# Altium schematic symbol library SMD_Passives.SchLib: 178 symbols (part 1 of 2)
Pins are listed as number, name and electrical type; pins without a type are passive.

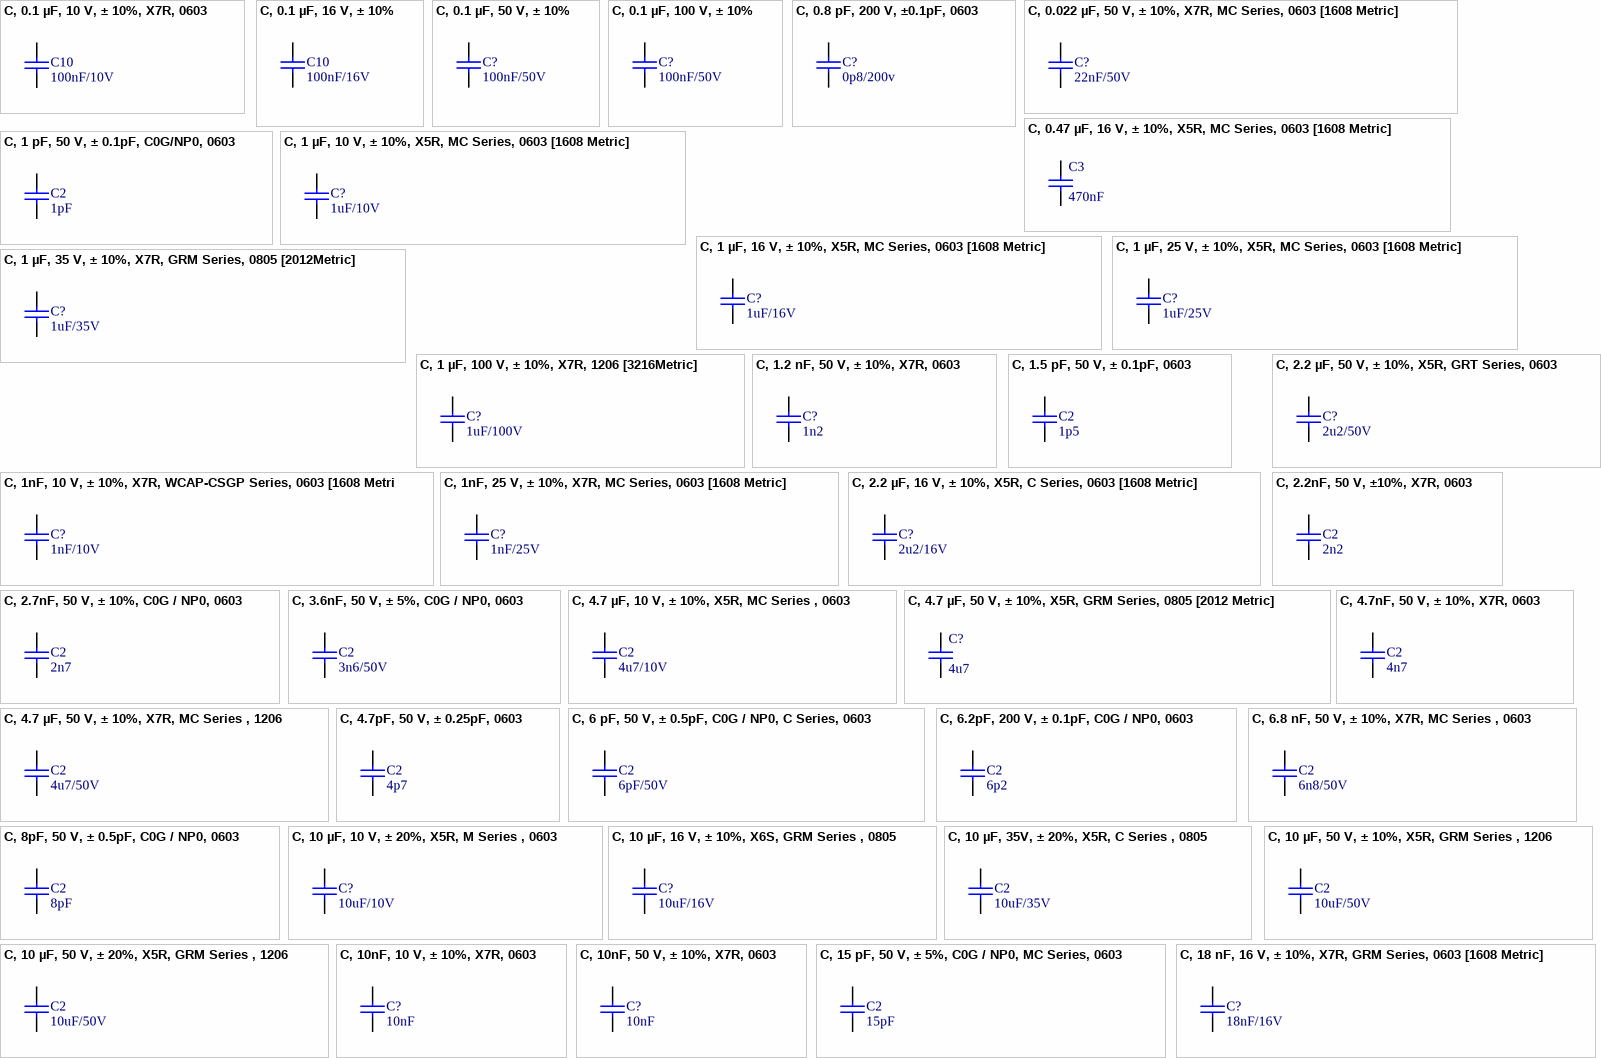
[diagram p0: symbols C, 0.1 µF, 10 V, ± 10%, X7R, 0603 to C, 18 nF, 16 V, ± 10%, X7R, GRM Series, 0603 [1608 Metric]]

## C, 0.1 µF, 10 V, ± 10%, X7R, 0603
designator C10, comment 100nF/10V
SMD Multilayer Ceramic Capacitor, 0603 [1608 Metric], 0.1 µF, 10 V, ± 10%, X7R, MC Series; MPN: MC0603B104K100CT; Type: MLCC; VoltageRating: 10V; MF: Multicomp; Capacitance: 100nF
footprint C0603 (0603 ceramic capacitor)
footprint C0603_BYPADD
footprint C0603_BYPASS
pins: 1, 2

## C, 0.1 µF, 16 V, ± 10%
designator C10, comment 100nF/16V
SMD Multilayer Ceramic Capacitor, 0603 [1608 Metric], 0.1 µF, 16 V, ± 10%, X7R, MC Series; MPN: MC0603B104K160CT; Type: MLCC; VoltageRating: 16V; ComponentLinknDescription: Datasheet; MF: Multicomp; Capacitance: 100nF
footprint C0603 (0603 ceramic capacitor)
footprint C0603_BYPADD
footprint C0603_BYPASS
pins: 1, 2

## C, 0.1 µF, 50 V, ± 10%
designator C?, comment 100nF/50V
SMD Multilayer Ceramic Capacitor, 0603 [1608 Metric], 0.1 µF, 50 V, ± 10%, X7R, MC Series; MPN: 885012206095; Type: MLCC; VoltageRating: 50V; ComponentLinknDescription: Datasheet; MF: Wurth Electronics; Capacitance: 100nF
footprint C0603 (0603 ceramic capacitor)
footprint C0603_BYPADD
footprint C0603_BYPASS
pins: 1, 2

## C, 0.1 µF, 100 V, ± 10%
designator C?, comment 100nF/50V
SMD Multilayer Ceramic Capacitor, 1812 [4532 Metric], 0.1 µF, 100 V, ± 5%, C0G / NP0, C Series; MPN: 885012206095; Type: MLCC; VoltageRating: 50V; ComponentLinknDescription: Datasheet; MF: Wurth Electronics; Capacitance: 100nF; Precision: 10%
footprint C1812 (1812 capacitor)
pins: 1, 2

## C, 0.8 pF, 200 V, ±0.1pF, 0603
designator C?, comment 0p8/200v
SMD Multilayer Ceramic Capacitor, 0603 [1608 Metric], 0.8 pF, 2000 V, ±0.1pF, C0G; MPN: 06032U0R8BAT2A; Type: MLCC; VoltageRating: 200v; ComponentLinknDescription: Datasheet; MF: AVX; Capacitance: 0p8
footprint C0603 (0603 ceramic capacitor)
pins: 1, 2

## C, 0.022 µF, 50 V, ± 10%, X7R, MC Series, 0603 [1608 Metric]
designator C?, comment 22nF/50V
SMD Multilayer Ceramic Capacitor, 0603 [1608 Metric], 0.022 µF, 50 V, ± 10%, X7R, MC Series; MPN: MC0603B223K500CT; Type: MLCC; VoltageRating: 50V; MF: MULTICOMP; Capacitance: 22nF
footprint C0603 (0603 ceramic capacitor)
pins: 1, 2

## C, 0.47 µF, 16 V, ± 10%, X5R, MC Series, 0603 [1608 Metric]
designator C3, comment 470nF
SMD Multilayer Ceramic Capacitor, 0603 [1608 Metric], 0.47 µF, 16 V, ± 10%, X5R, MC Series; MPN: MC0603X474K160CT; Type: MLCC; Voltage rating: 16V; ComponentLinknDescription: Datasheet; MF: Multicomp
footprint C0603 (0603 ceramic capacitor)
pins: 1, 2

## C, 1 pF, 50 V, ± 0.1pF, C0G/NP0, 0603
designator C2, comment 1pF
SMD Multilayer Ceramic Capacitor, 0603 [1608 Metric], 1 pF, 50 V, ± 0.1pF, C0G / NP0, GRM Series; MPN: GRM1885C1H1R0BA01D; Type: MLCC; VoltageRating: 50V; MF: MURATA
footprint C0603 (0603 ceramic capacitor)
pins: 1, 2

## C, 1 µF, 10 V, ± 10%, X5R, MC Series, 0603 [1608 Metric]
designator C?, comment 1uF/10V
SMD Multilayer Ceramic Capacitor, 0603 [1608 Metric], 1 µF, 10 V, ± 10%, X5R, MC Series; MPN: MC0603X105K100CT; Type: MLCC; VoltageRating: 10V; MF: MULTICOMP; Capacitance: 1uF
footprint C0603 (0603 ceramic capacitor)
pins: 1, 2

## C, 1 µF, 16 V, ± 10%, X5R, MC Series, 0603 [1608 Metric]
designator C?, comment 1uF/16V
SMD Multilayer Ceramic Capacitor, 0603 [1608 Metric], 1 µF, 16 V, ± 10%, X5R, MC Series; MPN: MC0603X105K160CT; Type: MLCC; VoltageRating: 16V; MF: MULTICOMP; Capacitance: 1uF
footprint C0603 (0603 ceramic capacitor)
pins: 1, 2

## C, 1 µF, 25 V, ± 10%, X5R, MC Series, 0603 [1608 Metric]
designator C?, comment 1uF/25V
SMD Multilayer Ceramic Capacitor, 0603 [1608 Metric], 1 µF, 25 V, ± 10%, X5R, MC Series; MPN: MC0603X105K250CT; Type: MLCC; VoltageRating: 25V; MF: MULTICOMP; Capacitance: 1uF
footprint C0603 (0603 ceramic capacitor)
pins: 1, 2

## C, 1 µF, 35 V, ± 10%, X7R, GRM Series, 0805 [2012Metric]
designator C?, comment 1uF/35V
SMD Multilayer Ceramic Capacitor, 0805 [2012 Metric], 1 µF, 35 V, ± 10%, X7R, GCM Series; MPN: GCM21BR7YA105KA55L; Type: MLCC; VoltageRating: 35V; MF: MURATA; Capacitance: 1uF
footprint C0603 (0603 ceramic capacitor)
pins: 1, 2

## C, 1 µF, 100 V, ± 10%, X7R, 1206 [3216Metric]
designator C?, comment 1uF/100V
SMD Multilayer Ceramic Capacitor, 1206 [3216 Metric], 1 µF, 100 V, ± 10%, X7R; MPN: 12061C105KAT2A; Type: MLCC; VoltageRating: 100V; MF: AVX; Capacitance: 1uF
footprint C1206 (1206 ceramic capacitor)
pins: 1, 2

## C, 1.2 nF, 50 V, ± 10%, X7R, 0603
designator C?, comment 1n2
SMD Multilayer Ceramic Capacitor, General Purpose, 0603 [1608 Metric], 1200 pF, 50 V, ± 10%, X7R; MPN: 0603B122K500CT; Type: MLCC; VoltageRating: 50V; MF: WALSIN
footprint C0603 (0603 ceramic capacitor)
pins: 1, 2

## C, 1.5 pF, 50 V, ± 0.1pF, 0603
designator C2, comment 1p5
SMD Multilayer Ceramic Capacitor, Hi-Q®, 0603 [1608 Metric], 1.5 pF, 250 V, ± 0.1pF, ML Series; MPN: ML03V11R5BAT2A; Type: MLCC; VoltageRating: 50V; MF: AVX
footprint C0603 (0603 ceramic capacitor)
pins: 1, 2

## C, 1nF, 10 V, ± 10%, X7R, WCAP-CSGP Series, 0603 [1608 Metric]
designator C?, comment 1nF/10V
SMD Multilayer Ceramic Capacitor, 0603 [1608 Metric], 1000 pF, 25 V, ± 10%, X7R, MC Series; MPN: 885012206014; Type: MLCC; VoltageRating: 10V; MF: WURTH ELECTRONIC; Capacitance: 1nF
footprint C0603 (0603 ceramic capacitor)
pins: 1, 2

## C, 1nF, 25 V, ± 10%, X7R, MC Series, 0603 [1608 Metric]
designator C?, comment 1nF/25V
SMD Multilayer Ceramic Capacitor, 0603 [1608 Metric], 1000 pF, 25 V, ± 10%, X7R, MC Series; MPN: MC0603B102K250CT; Type: MLCC; VoltageRating: 25V; MF: MULTICOMP; Capacitance: 1nF
footprint C0603 (0603 ceramic capacitor)
pins: 1, 2

## C, 2.2 µF, 16 V, ± 10%, X5R, C Series, 0603 [1608 Metric]
designator C?, comment 2u2/16V
SMD Multilayer Ceramic Capacitor, 0603 [1608 Metric], 2.2 µF, 16 V, ± 10%, X5R, C Series; MPN: C0603C225K4PACTU; Type: MLCC; VoltageRating: 16V; MF: KEMET; Capacitance: 2u2
footprint C0603 (0603 ceramic capacitor)
pins: 1, 2

## C, 2.2 µF, 50 V, ± 10%, X5R, GRT Series, 0603
designator C?, comment 2u2/50V
SMD Multilayer Ceramic Capacitor, 0603 [1608 Metric], 2.2 µF, 50 V, ± 10%, X5R, GRT Series; MPN: GRT188R61H225KE13D; Type: MLCC; VoltageRating: 50V; MF: MURATA; Capacitance: 2u2
footprint C0603 (0603 ceramic capacitor)
pins: 1, 2

## C, 2.2nF, 50 V, ±10%, X7R, 0603
designator C2, comment 2n2
SMD Multilayer Ceramic Capacitor, 0603 [1608 Metric], 2200 pF, 50 V, ± 10%, X7R, MC Series; MPN: MC0603B222K500CT; Type: MLCC; VoltageRating: 50V; MF: MULTICOMP
footprint C0603 (0603 ceramic capacitor)
pins: 1, 2

## C, 2.7nF, 50 V, ± 10%, C0G / NP0, 0603
designator C2, comment 2n7
SMD Multilayer Ceramic Capacitor, 0603 [1608 Metric], 2700 pF, 50 V, ± 10%, X7R, MC Series; MPN: MC0603B272K500CT; Type: MLCC; VoltageRating: 50V; MF: MULTICOMP
footprint C0603 (0603 ceramic capacitor)
pins: 1, 2

## C, 3.6nF, 50 V, ± 5%, C0G / NP0, 0603
designator C2, comment 3n6/50V
SMD Multilayer Ceramic Capacitor, 0603 [1608 Metric], 3600 pF, 50 V, ± 5%, C0G / NP0, C Series; MPN: C1608C0G1H151J080AA; Type: MLCC; VoltageRating: 50V; MF: TDK; Capacitance: 3n6
footprint C0603 (0603 ceramic capacitor)
pins: 1, 2

## C, 4.7 µF, 10 V, ± 10%, X5R, MC Series , 0603
designator C2, comment 4u7/10V
SMD Multilayer Ceramic Capacitor, 0603 [1608 Metric], 4.7 µF, 10 V, ± 10%, X5R, MC Series; MPN: MC0603X475K100CT; Type: MLCC; VoltageRating: 10V; MF: MULTICOMP; Capacitance: 4u7
footprint C0603 (Footprint not found)
pins: 1, 2

## C, 4.7 µF, 50 V, ± 10%, X5R, GRM Series, 0805 [2012 Metric]
designator C?, comment 4u7
SMD Multilayer Ceramic Capacitor, 0805 [2012 Metric], 4.7 µF, 50 V, ± 10%, X5R, GRM Series; MPN: GRM21BR61H475KE51L; Type: MLCC; Voltage rating: 50V; ComponentLinknDescription: Datasheet; MF: MURATA
footprint C0805 (0805 ceramic capacitor)
pins: 1, 2

## C, 4.7 µF, 50 V, ± 10%, X7R, MC Series , 1206
designator C2, comment 4u7/50V
SMD Multilayer Ceramic Capacitor, 1206 [3216 Metric], 4.7 µF, 50 V, ± 10%, X7R, MC Series; MPN: MC1206B475K500CT; Type: MLCC; VoltageRating: 50V; MF: MULTICOMP; Capacitance: 4u7
footprint C1206 (1206 ceramic capacitor)
pins: 1, 2

## C, 4.7nF, 50 V, ± 10%, X7R, 0603
designator C2, comment 4n7
SMD Multilayer Ceramic Capacitor, 0603 [1608 Metric], 4700 pF, 50 V, ± 10%, X7R, MC Series; MPN: MC0603B472K500CT; Type: MLCC; VoltageRating: 50V; MF: MULTICOMP
footprint C0603 (0603 ceramic capacitor)
pins: 1, 2

## C, 4.7pF, 50 V, ± 0.25pF, 0603
designator C2, comment 4p7
SMD Multilayer Ceramic Capacitor, General Purpose, 0603 [1608 Metric], 4.7 pF, 50 V, ± 0.25pF; MPN: MC0603B471J500CT; Type: MLCC; VoltageRating: 50V; MF: MULTICOMP
footprint C0603 (0603 ceramic capacitor)
pins: 1, 2

## C, 6 pF, 50 V, ± 0.5pF, C0G / NP0, C Series, 0603
designator C2, comment 6pF/50V
SMD Multilayer Ceramic Capacitor, 0603 [1608 Metric], 6 pF, 50 V, ± 0.5pF, C0G / NP0, C Series; MPN: C1608C0G1H060D080AA; Type: MLCC; VoltageRating: 50V; MF: TDK; Capacitance: 6pF
footprint C0603 (Footprint not found)
pins: 1, 2

## C, 6.2pF, 200 V, ± 0.1pF, C0G / NP0, 0603
designator C2, comment 6p2
Multilayer Ceramic Capacitors MLCC - SMD/SMT 200V 6.2pF C0G 0603 .1pF Tol; MPN: 06032U6R2BAT2A; Characteristic: C0G/NP0; MF: AVX; Precision: 0.1pF
footprint C0603 (0603 ceramic capacitor)
pins: 1, 2

## C, 6.8 nF, 50 V, ± 10%, X7R, MC Series , 0603
designator C2, comment 6n8/50V
SMD Multilayer Ceramic Capacitor, 0603 [1608 Metric], 6800 pF, 50 V, ± 10%, X7R, MC Series; MPN: MC0603B682K500CT; Type: MLCC; VoltageRating: 50V; MF: MULTICOMP; Capacitance: 6n8
footprint C0603 (Footprint not found)
pins: 1, 2

## C, 8pF, 50 V, ± 0.5pF, C0G / NP0, 0603
designator C2, comment 8pF
SMD Multilayer Ceramic Capacitor, 0603 [1608 Metric], 8 pF, 50 V, ± 0.5pF, C0G / NP0, MC Series; MPN: MC0603N8R0D500CT; Type: MLCC; VoltageRating: 50; MF: MULTICOMP
footprint C0603 (0603 ceramic capacitor)
pins: 1, 2

## C, 10 µF, 10 V, ± 20%, X5R, M Series , 0603
designator C?, comment 10uF/10V
SMD Multilayer Ceramic Capacitor, 0603 [1608 Metric], 10 µF, 10 V, ± 20%, X5R, M Series; MPN: LMK107BBJ106MALT; Type: MLCC; VoltageRating: 10V; MF: TAIYO YUDEN; Capacitance: 10uF
footprint C0603 (0603 ceramic capacitor)
pins: 1, 2

## C, 10 µF, 16 V, ± 10%, X6S, GRM Series , 0805
designator C?, comment 10uF/16V
SMD Multilayer Ceramic Capacitor, 0603 [1608 Metric], 10 µF, 10 V, ± 20%, X5R, M SeriesSMD Multilayer Ceramic Capacitor, 0805 [2012 Metric], 10 µF, 16 V, ± 10%, X6S, GRM Series; MPN: GRM21BC81C106KE15L; Type: MLCC; VoltageRating: 16V; MF: MURATA; Capacitance: 10uF
footprint C0805 (0805 ceramic capacitor)
pins: 1, 2

## C, 10 µF, 35V, ± 20%, X5R, C Series , 0805
designator C2, comment 10uF/35V
SMD Multilayer Ceramic Capacitor, 0805 [2012 Metric], 10 µF, 35 V, ± 20%, X5R, C Series; MPN: C2012X5R1V106M085AC; Type: MLCC; VoltageRating: 35V; MF: TDK; Capacitance: 10uF
footprint C0805 (0805 ceramic capacitor)
pins: 1, 2

## C, 10 µF, 50 V, ± 10%, X5R, GRM Series , 1206
designator C2, comment 10uF/50V
SMD Multilayer Ceramic Capacitor, 1206 [3216 Metric], 10 µF, 50 V, ± 10%, X5R, C Series; MPN: C3216X5R1H106K160AB; Type: MLCC; VoltageRating: 50V; MF: TDK; Capacitance: 10uF
footprint C1206 (1206 ceramic capacitor)
pins: 1, 2

## C, 10 µF, 50 V, ± 20%, X5R, GRM Series , 1206
designator C2, comment 10uF/50V
SMD Multilayer Ceramic Capacitor, 1206 [3216 Metric], 10 µF, 50 V, ± 20%, X5R, GRM Series; MPN: GRM31CR61H106MA12L; Type: MLCC; VoltageRating: 50V; MF: MURATA; Capacitance: 10uF
footprint C1206 (1206 ceramic capacitor)
pins: 1, 2

## C, 10nF, 10 V, ± 10%, X7R, 0603
designator C?, comment 10nF
SMD Multilayer Ceramic Capacitor, 0603 [1608 Metric], 0.01 µF, 10 V, ± 10%, X7R, MCSH Series; MPN: MCSH18B103K100CT; Type: MLCC; VoltageRating: 10V; MF: MULTICOMP
footprint C0603 (0603 ceramic capacitor)
pins: 1, 2

## C, 10nF, 50 V, ± 10%, X7R, 0603
designator C?, comment 10nF
SMD Multilayer Ceramic Capacitor, 0603 [1608 Metric], 0.01 µF, 50 V, ± 10%, X7R, MC Series; MPN: MC0603B103K500CT; Type: MLCC; VoltageRating: 50V; MF: MULTICOMP
footprint C0603 (0603 ceramic capacitor)
pins: 1, 2

## C, 15 pF, 50 V, ± 5%, C0G / NP0, MC Series, 0603
designator C2, comment 15pF
SMD Multilayer Ceramic Capacitor, 0603 [1608 Metric], 15 pF, 50 V, ± 5%, C0G / NP0, MC Series; MPN: MC0603N150J500CT; Type: MLCC; VoltageRating: 50V; MF: MULTICOMP
footprint C0603 (0603 ceramic capacitor)
pins: 1, 2

## C, 18 nF, 16 V, ± 10%, X7R, GRM Series, 0603 [1608 Metric]
designator C?, comment 18nF/16V
SMD Multilayer Ceramic Capacitor, 0603 [1608 Metric], 18 nF, 16 V, ± 10%, X7R, GRM Series; MPN: GRM188R71C183KA01D; Type: MLCC; VoltageRating: 16V; MF: MURATA; Capacitance: 18nF
footprint C0603 (0603 ceramic capacitor)
pins: 1, 2

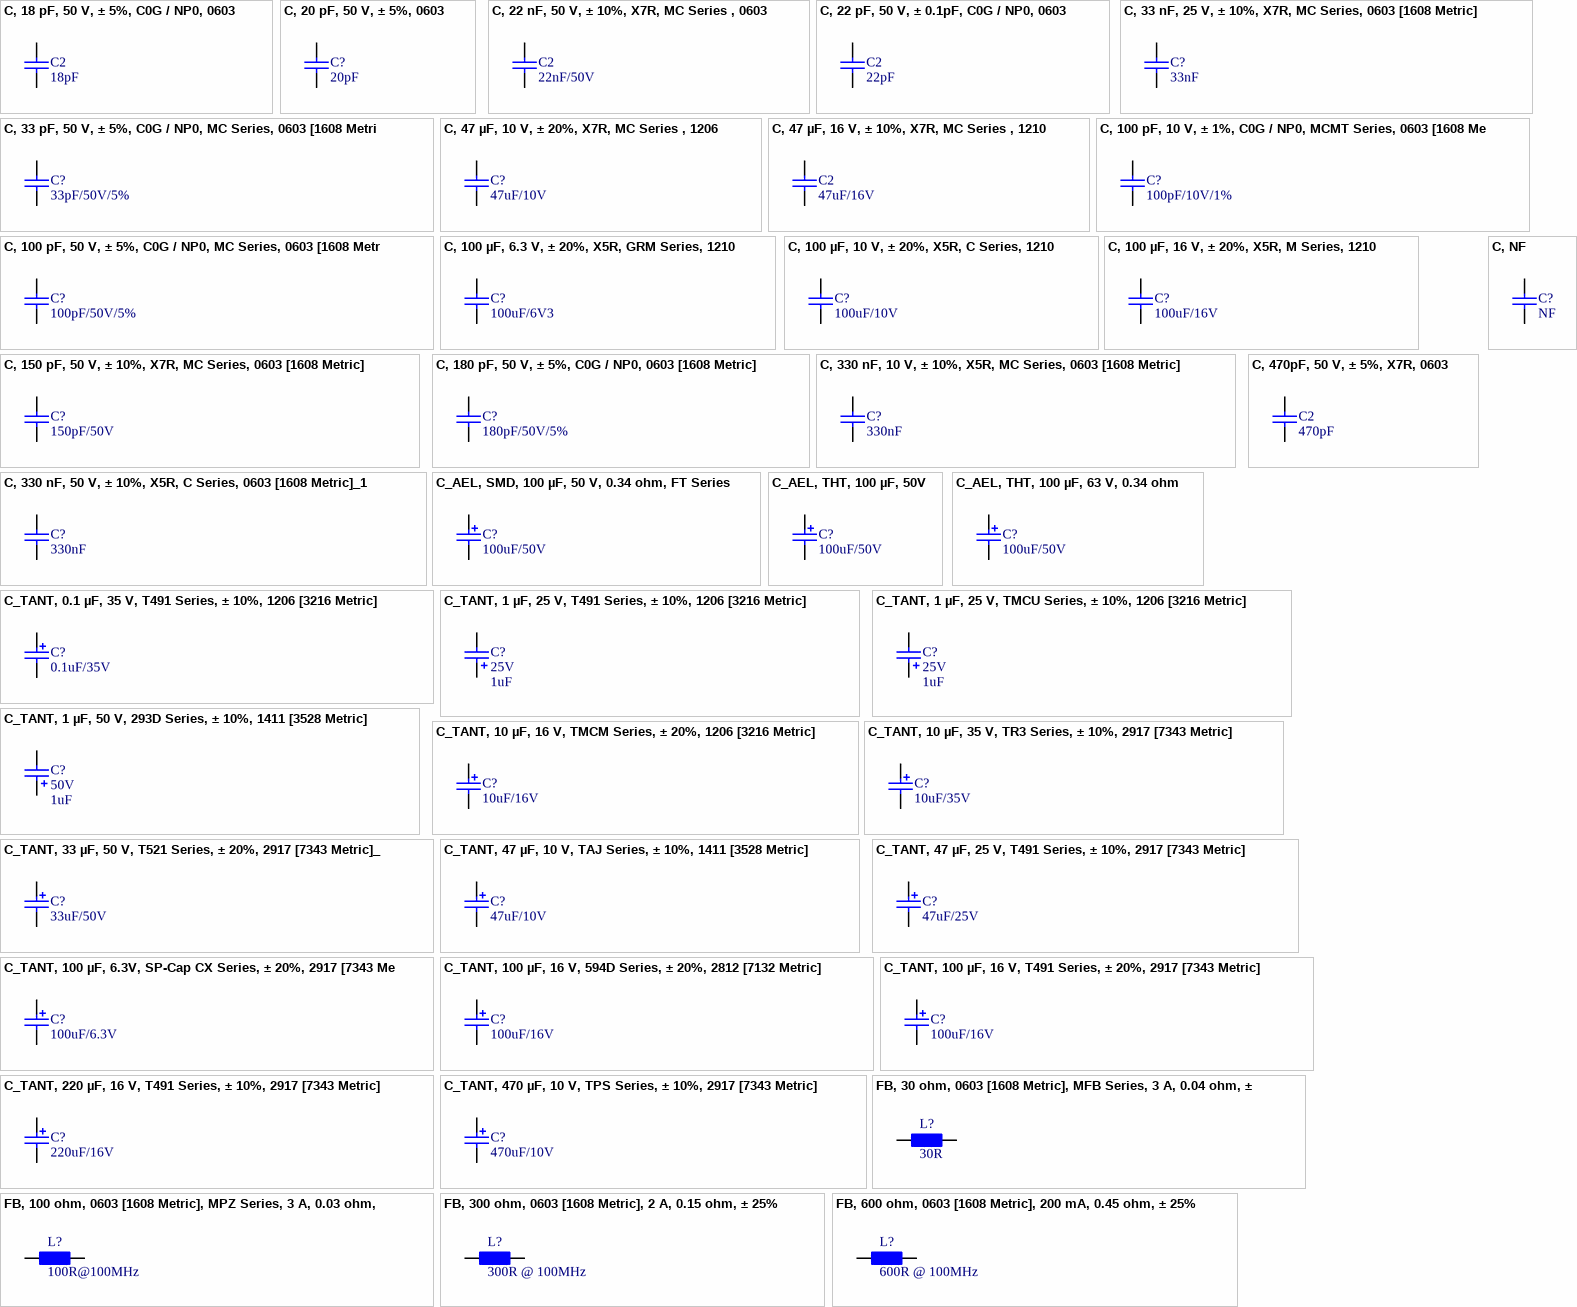
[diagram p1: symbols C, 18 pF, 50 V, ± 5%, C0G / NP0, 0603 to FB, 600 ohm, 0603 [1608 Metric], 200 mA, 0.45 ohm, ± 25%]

## C, 18 pF, 50 V, ± 5%, C0G / NP0, 0603
designator C2, comment 18pF
SMD Multilayer Ceramic Capacitor, 0603 [1608 Metric], 18 pF, 50 V, ± 5%, C0G / NP0, MC Series; MPN: MC0603N180J500CT; Type: MLCC; VoltageRating: 50V; MF: MULTICOMP
footprint C0603 (0603 ceramic capacitor)
pins: 1, 2

## C, 20 pF, 50 V, ± 5%, 0603
designator C?, comment 20pF
SMD Multilayer Ceramic Capacitor, General Purpose, 0603 [1608 Metric], 20 pF, 50 V, ± 5%, C0G / NP0; MPN: 0603N200J500CT; Type: MLCC; VoltageRating: 50V; MF: WALSIN
footprint C0603 (0603 ceramic capacitor)
pins: 1, 2

## C, 22 nF, 50 V, ± 10%, X7R, MC Series , 0603
designator C2, comment 22nF/50V
SMD Multilayer Ceramic Capacitor, 1206 [3216 Metric], 0.22 µF, 50 V, ± 10%, X7R, MC Series; MPN: MC1206B224K500CT; Type: MLCC; VoltageRating: 50V; MF: MULTICOMP; Capacitance: 22nF
footprint C0603 (Footprint not found)
pins: 1, 2

## C, 22 pF, 50 V, ± 0.1pF, C0G / NP0, 0603
designator C2, comment 22pF
SMD Multilayer Ceramic Capacitor, 0603 [1608 Metric], 22 pF, 50 V, ± 10%, C0G / NP0, MC Series; MPN: MC0603N220K500CT; Type: MLCC; VoltageRating: 50V; MF: MULTICOMP; Precision: 1%
footprint C0603 (0603 ceramic capacitor)
pins: 1, 2

## C, 33 nF, 25 V, ± 10%, X7R, MC Series, 0603 [1608 Metric]
designator C?, comment 33nF
SMD Multilayer Ceramic Capacitor, 0603 [1608 Metric], 0.033 µF, 25 V, ± 10%, X7R; MPN: 0603B333K250CT; Type: MLCC; VoltageRating: 25V; MF: WALSIN
footprint C0603 (0603 ceramic capacitor)
pins: 1, 2

## C, 33 pF, 50 V, ± 5%, C0G / NP0, MC Series, 0603 [1608 Metric]
designator C?, comment 33pF/50V/5%
SMD Multilayer Ceramic Capacitor, 0603 [1608 Metric], 33 pF, 50 V, ± 5%, C0G / NP0, MC Series; MPN: MC0603N330J500CT; Type: MLCC; VoltageRating: 50V; MF: MULTICOMP; Capacitance: 33pF
footprint C0603 (0603 ceramic capacitor)
pins: 1, 2

## C, 47 µF, 10 V, ± 20%, X7R, MC Series , 1206
designator C?, comment 47uF/10V
SMD Multilayer Ceramic Capacitor, 1206 [3216 Metric], 47 µF, 10 V, ± 20%, X5R, GRM Series; MPN: GRM31CR61A476ME15L; Type: MLCC; VoltageRating: 10V; MF: MURATA; Capacitance: 47uF
footprint C1206 (1206 ceramic capacitor)
pins: 1, 2

## C, 47 µF, 16 V, ± 10%, X7R, MC Series , 1210
designator C2, comment 47uF/16V
SMD Multilayer Ceramic Capacitor, 1210 [3225 Metric], 47 µF, 16 V, ± 20%, X5R, GRM Series; MPN: GRM32ER61C476ME15L; Type: MLCC; VoltageRating: 16V; Characteristic: X7R; MF: MURATA; Capacitance: 47uF; Precision: 10%
footprint C1210 (1210 capacitor)
pins: 1, 2

## C, 100 pF, 10 V, ± 1%, C0G / NP0, MCMT Series, 0603 [1608 Metric]
designator C?, comment 100pF/10V/1%
SMD Multilayer Ceramic Capacitor, 0603 [1608 Metric], 100 pF, 10 V, ± 1%, C0G / NP0, MCMT Series; MPN: MCMT18N101F100CT; Type: MLCC; VoltageRating: 10V; MF: MULTICOMP; Capacitance: 100pF
footprint C0603 (0603 ceramic capacitor)
pins: 1, 2

## C, 100 pF, 50 V, ± 5%, C0G / NP0, MC Series, 0603 [1608 Metric]
designator C?, comment 100pF/50V/5%
SMD Multilayer Ceramic Capacitor, 0603 [1608 Metric], 100 pF, 50 V, ± 5%, C0G / NP0, MC Series; MPN: MC0603N101J500CT; Type: MLCC; VoltageRating: 50V; MF: MULTICOMP; Capacitance: 100pF
footprint C0603 (0603 ceramic capacitor)
pins: 1, 2

## C, 100 µF, 6.3 V, ± 20%, X5R, GRM Series, 1210
designator C?, comment 100uF/6V3
SMD Multilayer Ceramic Capacitor, 1210 [3225 Metric], 100 µF, 6.3 V, ± 20%, X5R, GRM Series; MPN: GRM31CR60J107ME39L.; Type: MLCC; VoltageRating: 6V3; MF: MURATA; Capacitance: 100uF
footprint C1210 (1210 capacitor)
pins: 1, 2

## C, 100 µF, 10 V, ± 20%, X5R, C Series, 1210
designator C?, comment 100uF/10V
SMD Multilayer Ceramic Capacitor, 1210 [3225 Metric], 100 µF, 10 V, ± 20%, X5R, C Series; MPN: C1210C107M8PACTU; Type: MLCC; VoltageRating: 10V; MF: KEMET; Capacitance: 100uF
footprint C1210 (1210 capacitor)
pins: 1, 2

## C, 100 µF, 16 V, ± 20%, X5R, M Series, 1210
designator C?, comment 100uF/16V
SMD Multilayer Ceramic Capacitor, 1210 [3225 Metric], 100 µF, 16 V, ± 20%, X5R, M Series; MPN: EMK325ABJ107MM-T; Type: MLCC; VoltageRating: 16V; MF: TAIYO YUDEN; Capacitance: 100uF
footprint C1210 (1210 capacitor)
pins: 1, 2

## C, 150 pF, 50 V, ± 10%, X7R, MC Series, 0603 [1608 Metric]
designator C?, comment 150pF/50V
SMD Multilayer Ceramic Capacitor, 0603 [1608 Metric], 150 pF, 50 V, ± 10%, X7R, MC Series; MPN: MC0603B151K500CT; Type: MLCC; VoltageRating: 50V; MF: MULTICOMP; Capacitance: 150pF
footprint C0603 (0603 ceramic capacitor)
pins: 1, 2

## C, 180 pF, 50 V, ± 5%, C0G / NP0, 0603 [1608 Metric]
designator C?, comment 180pF/50V/5%
SMD Multilayer Ceramic Capacitor, 0603 [1608 Metric], 180 pF, 50 V, ± 5%, C0G / NP0; MPN: 0603N181J500CT; Type: MLCC; VoltageRating: 50V; MF: WALSIN; Capacitance: 180pF
footprint C0603 (0603 ceramic capacitor)
pins: 1, 2

## C, 330 nF, 10 V, ± 10%, X5R, MC Series, 0603 [1608 Metric]
designator C?, comment 330nF
SMD Multilayer Ceramic Capacitor, 0603 [1608 Metric], 0.33 µF, 10 V, ± 10%, X5R, MC Series; MPN: MC0603X334K100CT; Type: MLCC; VoltageRating: 10V; Characteristic: C0G / NP0; MF: MULTICOMP
footprint C0603 (0603 ceramic capacitor)
pins: 1, 2

## C, 330 nF, 50 V, ± 10%, X5R, C Series, 0603 [1608 Metric]_1
designator C?, comment 330nF
SMD Multilayer Ceramic Capacitor, 0603 [1608 Metric], 0.33 µF, 50 V, ± 10%, X5R, C Series; MPN: C1608X5R1H334K080AB; Type: MLCC; VoltageRating: 50V; MF: TDK
footprint C0603 (0603 ceramic capacitor)
pins: 1, 2

## C, 470pF, 50 V, ± 5%, X7R, 0603
designator C2, comment 470pF
SMD Multilayer Ceramic Capacitor, 0603 [1608 Metric], 470 pF, 50 V, ± 5%, X7R, MC Series; MPN: MC0603B471J500CT; Type: MLCC; VoltageRating: 50V; Characteristic: C0G/NP0; MF: MULTICOMP
footprint C0603 (0603 ceramic capacitor)
pins: 1, 2

## C, NF
designator C?, comment NF
Not fitted; Type: MLCC
footprint C0603 (0603 ceramic capacitor)
pins: 1, 2

## C_AEL, SMD, 100 µF, 50 V, 0.34 ohm, FT Series
designator C?, comment 100uF/50V
SMD Aluminium Electrolytic Capacitor, Radial Can - SMD, 100 µF, 50 V, 0.34 ohm, FT Series; MPN: EEEFTH101XAP; Type: MLCC; VoltageRating: 50V; MF: PANASONIC ELECTRONIC COMPONENTS; Capacitance: 100uF
footprint EEEFTH101XAP (Aluminum Electrolytic Capacitor, Body 6,60x6,60x8,00mm, IPC High Density)
pins: 1, 2

## C_AEL, THT, 100 µF, 50V
designator C?, comment 100uF/50V
Capacitor: electrolytic; THT; 100uF; 50VDC; Ø8x12mm; Pitch:3.5mm; MPN: CE-100/50PHT-Y; VoltageRating: 50V; MF: AISHI; Precision: ±20%
footprint CAP_AEL, THT, 3.5, PF1H101MNN08B5 (Capacitor: electrolytic; THT; 100uF; 50VDC; Ø8x11.5mm; Pitch:3.5mm)
pins: 1, 2

## C_AEL, THT, 100 µF, 63 V, 0.34 ohm
designator C?, comment 100uF/50V
Capacitor: electrolytic; THT; 100uF; 50VDC; Ø8x11.5mm; Pitch:3.5mm; MPN: PF1H101MNN08B5; VoltageRating: 50V; MF: ELITE; Precision: ±20%
footprint CAP_AEL, THT, 3.5, PF1H101MNN08B5 (Capacitor: electrolytic; THT; 100uF; 50VDC; Ø8x11.5mm; Pitch:3.5mm)
pins: 1, 2

## C_TANT, 0.1 µF, 35 V, T491 Series, ± 10%, 1206 [3216 Metric]
designator C?, comment 0.1uF/35V
Surface Mount Tantalum Capacitor, 0.1 µF, 35 V, T491 Series, ± 10%, 1206 [3216 Metric]; MPN: T491A104K035AT; VoltageRating: 35V; MF: KEMET; Capacitance: 0.1uF
footprint TAN_A_S (Capacitor, SM Tantalum; Body 3.2 x 1.6 mm (LxW typ))
pins: 1, 2

## C_TANT, 1 µF, 25 V, T491 Series, ± 10%, 1206 [3216 Metric]
designator C?, comment Voltage rating: 25V  (hidden comment: 1uF)
Polarized Capacitor; MPN: T491A105K025AT; ComponentLinknDescription: Datasheet; ESR: 8R; MF: Kemet
footprint TAN_A_S (Capacitor, SM Tantalum; Body 3.2 x 1.6 mm (LxW typ))
pins: 1, 2
1 alternate drawing of the same symbol

## C_TANT, 1 µF, 25 V, TMCU Series, ± 10%, 1206 [3216 Metric]
designator C?, comment Voltage rating: 25V  (hidden comment: 1uF)
Surface Mount Tantalum Capacitor, 1 µF, 25 V, TMCU Series, ± 10%, 1206 [3216 Metric]; MPN: TMCUA1E105KTRF; ComponentLinknDescription: Datasheet; ESR: 16.5R; MF: VISHAY
footprint TAN_A_S (Capacitor, SM Tantalum; Body 3.2 x 1.6 mm (LxW typ))
pins: 1, 2
1 alternate drawing of the same symbol

## C_TANT, 1 µF, 50 V, 293D Series, ± 10%, 1411 [3528 Metric]
designator C?, comment Voltage rating: 50V  (hidden comment: 1uF)
Surface Mount Tantalum Capacitor, TANTAMOUNT®, 1 µF, 50 V, 293D Series, ± 10%, 1411 [3528 Metric]; MPN: 293D105X9050B2TE3; ComponentLinknDescription: Datasheet; ESR: 6.7R; MF: VISHAY
footprint TAN_B_T (Capacitor, SM Tantalum; Body 3.5 x 2.8 mm (LxW typ))
pins: 1, 2
1 alternate drawing of the same symbol

## C_TANT, 10 µF, 16 V, TMCM Series, ± 20%, 1206 [3216 Metric]
designator C?, comment 10uF/16V
Cap Tant Solid 10uF 16V A CASE 20% (3.2 X 1.6 X 1.6mm) SMD 3216-18 2.9 Ohm 125°C T/R; MPN: TMCMA1C106MTRF; Type: MLCC; MF: Vishay / Sprague
footprint TAN_A_S (Capacitor, SM Tantalum; Body 3.2 x 1.6 mm (LxW typ))
pins: 1, 2

## C_TANT, 10 µF, 35 V, TR3 Series, ± 10%, 2917 [7343 Metric]
designator C?, comment 10uF/35V
Surface Mount Tantalum Capacitor, TANTAMOUNT®, 10 µF, 35 V, TR3 Series, ± 10%, 2917 [7343 Metric]; MPN: TR3E106K035C0200; Type: MLCC; VoltageRating: 35V; MF: VISHAY; Capacitance: 10uF; Precision: 20%
footprint TAN_X/E (Capacitor, SM Tantalum; Body 7.3 x 4.3 mm (LxW typ))
pins: 1, 2

## C_TANT, 33 µF, 50 V, T521 Series, ± 20%, 2917 [7343 Metric]_1
designator C?, comment 33uF/50V
Surface Mount Tantalum Capacitor, 33 µF, 50 V, T521 Series, ± 20%, 2917 [7343 Metric]; MPN: T521X336M050ATE075; Type: MLCC; VoltageRating: 50V; MF: KEMET; Capacitance: 33uF
footprint TAN_X/E (Capacitor, SM Tantalum; Body 7.3 x 4.3 mm (LxW typ))
pins: 1, 2

## C_TANT, 47 µF, 10 V, TAJ Series, ± 10%, 1411 [3528 Metric]
designator C?, comment 47uF/10V
Surface Mount Tantalum Capacitor, 47 µF, 25 V, T491 Series, ± 10%, 2917 [7343 Metric]; MPN: TAJB476K010RNJ; Type: TANTAL; VoltageRating: 10V; MF: AVX; Capacitance: 47uF
footprint TAN_B_T (Capacitor, SM Tantalum; Body 3.5 x 2.8 mm (LxW typ))
pins: 1, 2

## C_TANT, 47 µF, 25 V, T491 Series, ± 10%, 2917 [7343 Metric]
designator C?, comment 47uF/25V
Surface Mount Tantalum Capacitor, 47 µF, 25 V, T491 Series, ± 10%, 2917 [7343 Metric]; MPN: T491X476K025AT; Type: TANTAL; VoltageRating: 25V; MF: KEMET; Capacitance: 47uF
footprint TAN_X/E (Capacitor, SM Tantalum; Body 7.3 x 4.3 mm (LxW typ))
pins: 1, 2

## C_TANT, 100 µF, 6.3V, SP-Cap CX Series, ± 20%, 2917 [7343 Metric]
designator C?, comment 100uF/6.3V
Capacitor, 100 µF, 6.3 V, SP-Cap CX Series, 2917 [7343 Metric], 0.015 ohm, 1000 hours @ 105°C; MPN: EEFCX0J101R; Type: Aluminium Polymer; VoltageRating: 6.3V; MF: PANASONIC ELECTRONIC COMPONENTS; Capacitance: 100uF; Precision: 20%
footprint TAN_CX (Capacitor, SM Tantalum; Body 7.3 x 4.3 mm (LxW typ))
pins: 1, 2

## C_TANT, 100 µF, 16 V, 594D Series, ± 20%, 2812 [7132 Metric]
designator C?, comment 100uF/16V
Surface Mount Tantalum Capacitor, TANTAMOUNT®, 100 µF, 16 V, 594D Series, ± 20%, 2812 [7132 Metric]; MPN: 594D107X0016C2T; VoltageRating: 16V; MF: VISHAY; Capacitance: 100uF
footprint C_TANT_594D Series_CASE_C
pins: 1, 2

## C_TANT, 100 µF, 16 V, T491 Series, ± 20%, 2917 [7343 Metric]
designator C?, comment 100uF/16V
Surface Mount Tantalum Capacitor, 100 µF, 16 V, T491 Series, ± 20%, 2917 [7343 Metric]; MPN: T491D107M016AT; Type: MLCC; VoltageRating: 16V; Characteristic: X5R; MF: KEMET; Capacitance: 100uF
footprint TAN_V/Y_D (Capacitor, SM Tantalum; Body 7.3 x 4.3 mm (LxW typ))
pins: 1, 2

## C_TANT, 220 µF, 16 V, T491 Series, ± 10%, 2917 [7343 Metric]
designator C?, comment 220uF/16V
Surface Mount Tantalum Capacitor, 220 µF, 16 V, T491 Series, ± 10%, 2917 [7343 Metric]; MPN: T491D227K016AT; VoltageRating: 16V; MF: KEMET; Capacitance: 220uF
pins: 1, 2

## C_TANT, 470 µF, 10 V, TPS Series, ± 10%, 2917 [7343 Metric]
designator C?, comment 470uF/10V
Tantalum Capacitors - Solid SMD 470uF 10V 10% L ESR; MPN: TPSE477K010R0100; Type: TANTAL; MF: AVX
footprint TAN_X/E (Capacitor, SM Tantalum; Body 7.3 x 4.3 mm (LxW typ))
pins: 1, 2

## FB, 30 ohm, 0603 [1608 Metric], MFB Series, 3 A, 0.04 ohm, ± 25%
designator L?, comment 30R
Ferrite Bead, 30 ohm, 0603 [1608 Metric], MFB Series, 3 A, 0.04 ohm, ± 25%; MPN: MFB-160808-0030PQ; MF: MEC MARCOM; DC Current Rating: 3A; DC Resistance Max:: 0R04
footprint L0603 (0603 inductor)
footprint L0402 (0402 inductor)
pins: 1, 2

## FB, 100 ohm, 0603 [1608 Metric], MPZ Series, 3 A, 0.03 ohm, ± 25%
designator L?, comment 100R@100MHz
Ferrite Bead, 100 ohm, 0603 [1608 Metric], MPZ Series, 3 A, 0.03 ohm, ± 25%; MPN: MPZ1608S101A; MF: TDK; DC Current Rating: 3A; DC Resistance Max:: 0.03R
footprint L0603 (0603 inductor)
footprint L0402 (0402 inductor)
pins: 1, 2

## FB, 300 ohm, 0603 [1608 Metric], 2 A, 0.15 ohm, ± 25%
designator L?, comment 300R @ 100MHz
Ferrite Bead, 300 ohm, 0603 [1608 Metric], 2 A, 0.15 ohm, ± 25%; MPN: 742792641; MF: WURTH ELEKTRONIK; DC Current Rating: 2A; DC Resistance Max:: 0R15
footprint L0603 (0603 inductor)
pins: 1, 2

## FB, 600 ohm, 0603 [1608 Metric], 200 mA, 0.45 ohm, ± 25%
designator L?, comment 600R @ 100MHz
Ferrite Bead, 600 ohm, 0603 [1608 Metric], 200 mA, 0.45 ohm, ± 25%; MPN: 74279265; MF: WURTH ELEKTRONIK; DC Current Rating: 200mA; DC Resistance Max:: 0R45
footprint L0603 (0603 inductor)
pins: 1, 2

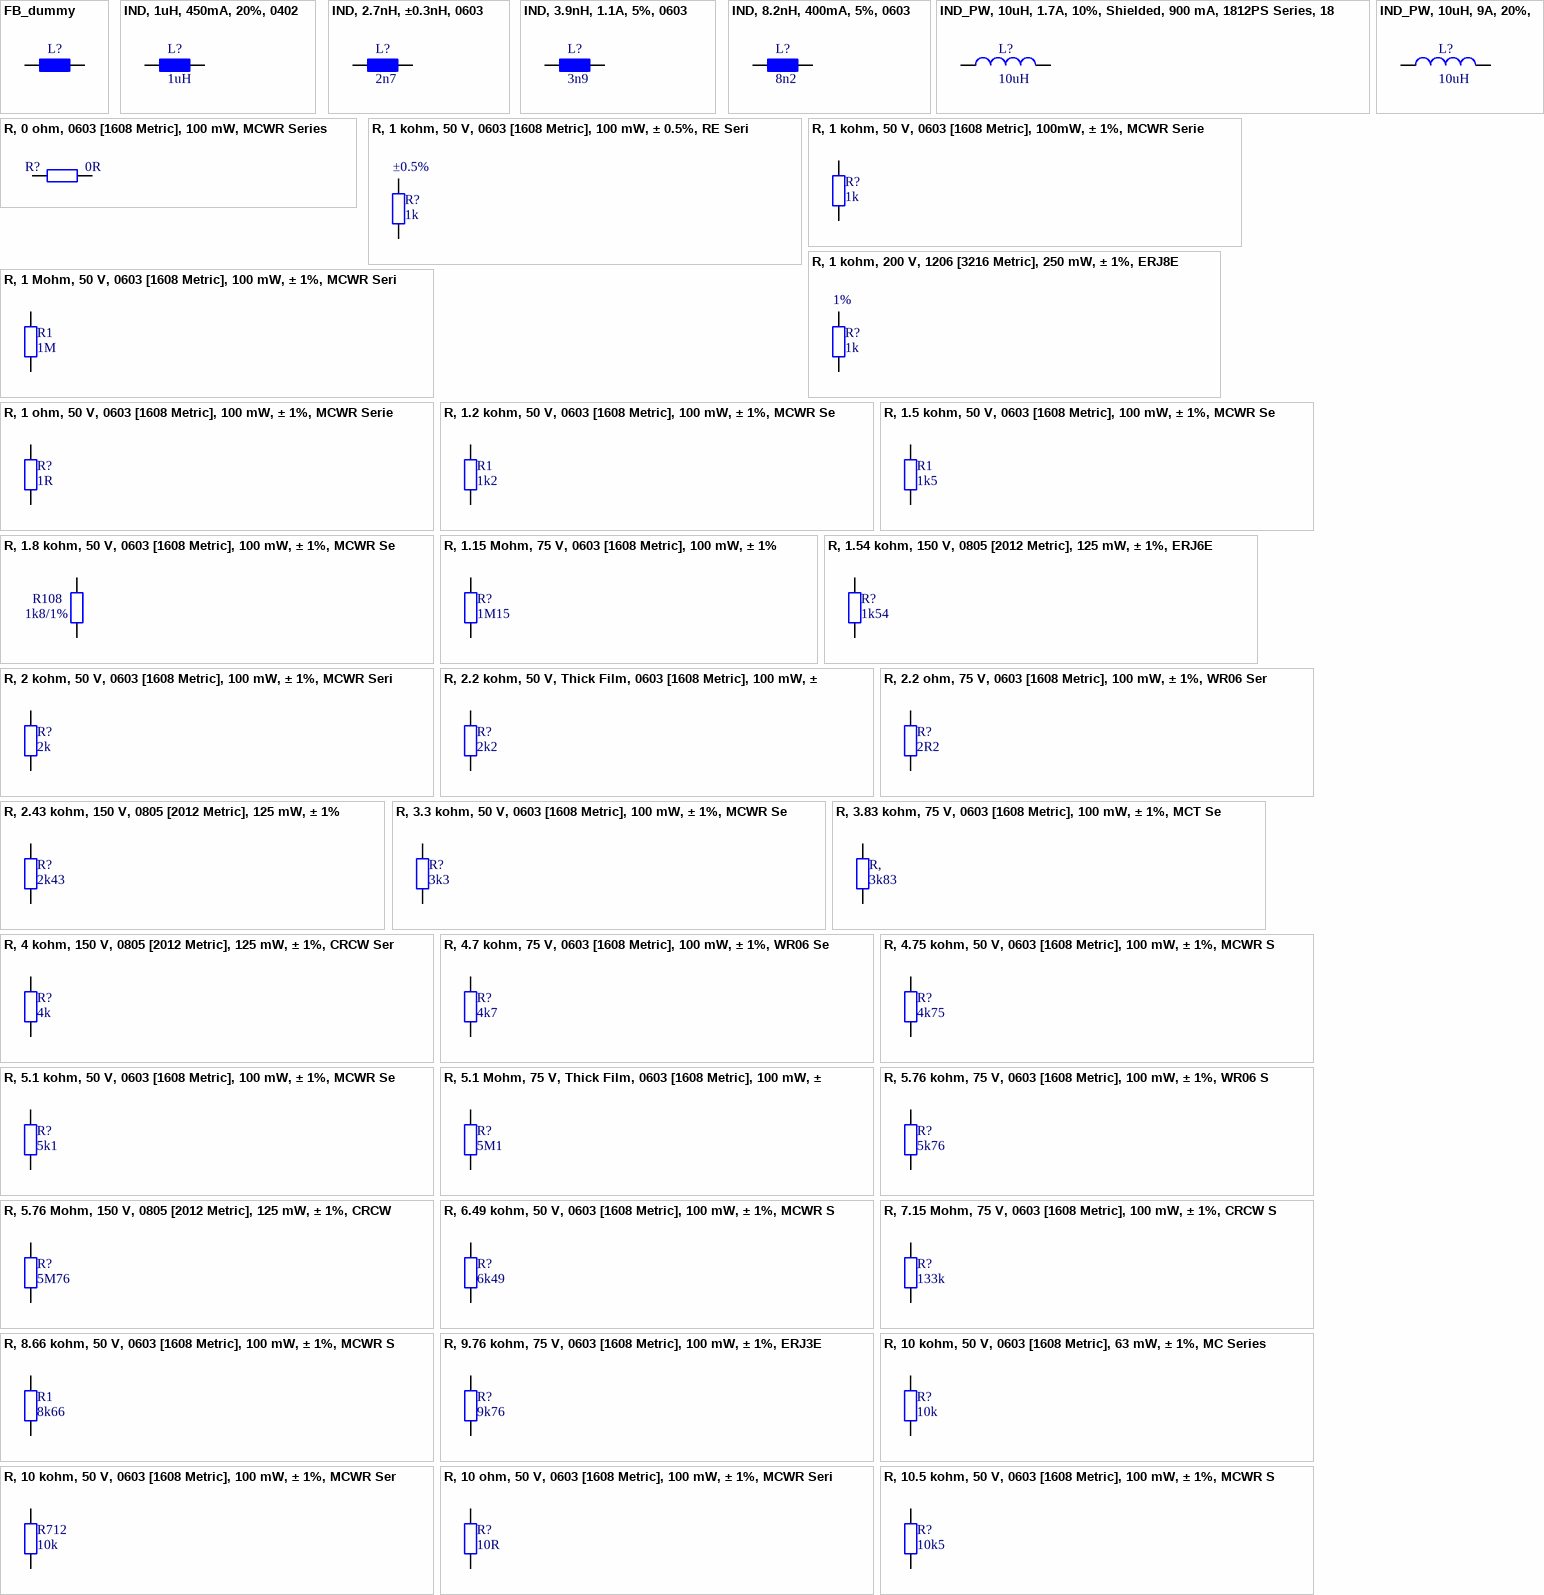
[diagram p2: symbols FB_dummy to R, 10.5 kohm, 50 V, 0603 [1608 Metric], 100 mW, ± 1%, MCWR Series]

## FB_dummy
designator L?
footprint L0603 (0603 inductor)
footprint L0402 (0402 inductor)
pins: 1, 2

## IND, 1uH, 450mA, 20%, 0402
designator L?, comment 1uH
Fixed Inductors 1 UH 20%; MPN: MLZ1005M1R0WT000; MF: TDK; DC Current Rating: 450mA; DC Resistance Max:: 0R35
footprint L0402 (0402 inductor)
pins: 1, 2

## IND, 2.7nH, ±0.3nH, 0603
designator L?, comment 2n7
Surface Mount High Frequency Inductor, B82496C Series, 2.7 nH, 0603 [1608 Metric]; MPN: LQG18HH2N7S00D; MF: MURATA; Tolerance: ±0.3nH; DC Current Rating: 1.1A; DC Resistance Max:: 0R065
footprint L0603 (0603 inductor)
pins: 1, 2

## IND, 3.9nH, 1.1A, 5%, 0603
designator L?, comment 3n9
Surface Mount High Frequency Inductor, B82496C Series, 3.9 nH, 1.1 A, 0603 [1608 Metric], Wirewound; MPN: B82496C3399J000; MF: EPCOS; Tolerance: ±5%; DC Current Rating: 1.1A; DC Resistance Max:: 0R065
footprint L0603 (0603 inductor)
pins: 1, 2

## IND, 8.2nH, 400mA, 5%, 0603
designator L?, comment 8n2
Surface Mount High Frequency Inductor, LQG18HN Series, 8.2 nH, 400 mA, 0603 [1608 Metric]; MPN: LQG18HN8N2J00D; MF: MURATA; Tolerance: ±5%; DC Current Rating: 400mA; DC Resistance Max:: 0R25
footprint L0603 (0603 inductor)
pins: 1, 2

## IND_PW, 10uH, 1.7A, 10%, Shielded, 900 mA, 1812PS Series, 1812 [4525 Metric]
designator L?, comment 10uH
Power Inductor (SMD), 10 µH, 1.7 A, Shielded, 900 mA, 1812PS Series, 1812 [4525 Metric]; MPN: 1812PS-103KLC; MF: COILCRAFT; Tolerance: ±10%; DC Resistance Max:: 0R17
footprint 1812PS-103KLC
pins: 1, 2

## IND_PW, 10uH, 9A, 20%,
designator L?, comment 10uH
Power Inductor (SMD), 10 µH, 9 A, 16 A, SRP1250 Series, 13.9mm x 13.5mm x 5.9mm, Shielded; MPN: SRP1250-100M; Tolerance: ±20%; DC Current Rating: 1.1A; DC Resistance Max:: 0R065
footprint SRP1250-100M (Power Inductor (SMD), 10 µH, 9 A, 16 A, SRP1250 Series, 13.9mm x 13.5mm x 5.9mm, Shielded)
pins: 1, 2

## R, 0 ohm, 0603 [1608 Metric], 100 mW, MCWR Series
designator R?, comment 0R
SMD Chip Resistor, Thick Film, 0 ohm, 0603 [1608 Metric], 100 mW, MCWR Series; MPN: MCWR06X000 PTL; Temp coefficient: *ppm; PowerRating: 100mW; MF: MULTICOMP
footprint R0402 (0402 resistor)
footprint R0603 (0603 resistor)
footprint R0805 (0805 resistor)
footprint R1206 (1206 resistor)
footprint R2512 (2512 resistor)
footprint R0201 (0201 resistor)
footprint R1210 (1210 resistor)
footprint R1812 (1812 resistor)
footprint R2010 (2010 resistor)
footprint R2512 (2512 resistor)
pins: 1, 2

## R, 1 kohm, 50 V, 0603 [1608 Metric], 100 mW, ± 0.5%, RE Series
designator R?, comment Precision: ±0.5%  (hidden comment: 1k)
SMD Chip Resistor, Thick Film, 1 kohm, 50 V, 0603 [1608 Metric], 100 mW, ± 0.5%, RE Series; MPN: RE0603DR-071KL; VoltageRating: 50V; Temp coefficient: *ppm; PowerRating: 100mW; MF: YAGEO (PHYCOMP)
footprint R0402 (0402 resistor)
footprint R0603 (0603 resistor)
footprint R0805 (0805 resistor)
footprint R1206 (1206 resistor)
footprint R2512 (2512 resistor)
footprint R0201 (0201 resistor)
footprint R1210 (1210 resistor)
footprint R1812 (1812 resistor)
footprint R2010 (2010 resistor)
footprint R2512 (2512 resistor)
pins: 1, 2

## R, 1 kohm, 50 V, 0603 [1608 Metric], 100mW, ± 1%, MCWR Series
designator R?, comment 1k
SMD Chip Resistor, Thick Film, 1 kohm, 50 V, 0603 [1608 Metric], 100 mW, ± 1%, MCWR Series; MPN: MCWR06X1001FTL; VoltageRating: 50V; Temp coefficient: *ppm; PowerRating: 100mW; MF: MULTICOMP
footprint R0603 (0603 resistor)
pins: 1, 2

## R, 1 kohm, 200 V, 1206 [3216 Metric], 250 mW, ± 1%, ERJ8E
designator R?, comment Precision: 1%  (hidden comment: 1k)
SMD Chip Resistor, Thick Film, 1 kohm, 50 V, 0603 [1608 Metric], 100 mW, ± 0.5%, RE Series; MPN: RE0603DR-071KL; VoltageRating: 200V; Temp coefficient: *ppm; PowerRating: 250mW; MF: YAGEO (PHYCOMP)
footprint R1206 (1206 resistor)
pins: 1, 2

## R, 1 Mohm, 50 V, 0603 [1608 Metric], 100 mW, ± 1%, MCWR Series
designator R1, comment 1M
SMD Chip Resistor, Thick Film, 1 Mohm, 50 V, 0603 [1608 Metric], 100 mW, ± 1%, MCWR Series; MPN: MCWR06X1004FTL; VoltageRating: 50V; Temp coefficient: *ppm; PowerRating: 100mW; MF: MULTICOMP
footprint R0603 (0603 resistor)
pins: 1, 2

## R, 1 ohm, 50 V, 0603 [1608 Metric], 100 mW, ± 1%, MCWR Series
designator R?, comment 1R
SMD Chip Resistor, Thick Film, 1 ohm, 50 V, 0603 [1608 Metric], 100 mW, ± 1%, MCWR Series; MPN: MCWR06W1R00FTL; VoltageRating: 50V; Temp coefficient: *ppm; PowerRating: 100mW; MF: MULTICOMP
footprint R0402 (0402 resistor)
footprint R0603 (0603 resistor)
footprint R0805 (0805 resistor)
footprint R1206 (1206 resistor)
footprint R2512 (2512 resistor)
footprint R0201 (0201 resistor)
footprint R1210 (1210 resistor)
footprint R1812 (1812 resistor)
footprint R2010 (2010 resistor)
footprint R2512 (2512 resistor)
pins: 1, 2

## R, 1.2 kohm, 50 V, 0603 [1608 Metric], 100 mW, ± 1%, MCWR Series
designator R1, comment 1k2
SMD Chip Resistor, Thick Film, 1.2 kohm, 50 V, 0603 [1608 Metric], 100 mW, ± 1%, MCWR Series; MPN: MCWR06X1201FTL; VoltageRating: 50V; Temp coefficient: *ppm; PowerRating: 100mW; MF: MULTICOMP
footprint R0603 (0603 resistor)
pins: 1, 2

## R, 1.5 kohm, 50 V, 0603 [1608 Metric], 100 mW, ± 1%, MCWR Series
designator R1, comment 1k5
SMD Chip Resistor, Thick Film, 1.5 kohm, 50 V, 0603 [1608 Metric], 100 mW, ± 1%, MCWR Series; MPN: MCWR06X1501FTL; VoltageRating: 50V; Temp coefficient: *ppm; PowerRating: 63mW; MF: MULTICOMP
footprint R0603 (0603 resistor)
pins: 1, 2

## R, 1.8 kohm, 50 V, 0603 [1608 Metric], 100 mW, ± 1%, MCWR Series
designator R108, comment 1k8/1%
SMD Chip Resistor, Thick Film, 1.8 kohm, 50 V, 0603 [1608 Metric], 100 mW, ± 1%, MCWR Series; MPN: MCWR06X1801FTL; Voltage rating: 50V; Temp coefficient: *ppm; Power rating: 100mW; MF: MULTICOMP; ComponentLinknDescription: Datasheet; Resistance: 1k8
footprint R0402 (0402 resistor)
footprint R0603 (0603 resistor)
footprint R0805 (0805 resistor)
footprint R1206 (1206 resistor)
footprint R2512 (2512 resistor)
footprint R0201 (0201 resistor)
footprint R1210 (1210 resistor)
footprint R1812 (1812 resistor)
footprint R2010 (2010 resistor)
footprint R2512 (2512 resistor)
pins: 1, 2

## R, 1.15 Mohm, 75 V, 0603 [1608 Metric], 100 mW, ± 1%
designator R?, comment 1M15
SMD Chip Resistor, 1.15 Mohm, MC Series, 75 V, Thick Film, 0603 [1608 Metric], 100 mW; MPN: RC0603FR-071M15L; Precision: 1%; VoltageRating: 75V; Temp coefficient: *ppm; PowerRating: 100mW; MF: YAEGO
footprint R0603 (0603 resistor)
pins: 1, 2

## R, 1.54 kohm, 150 V, 0805 [2012 Metric], 125 mW, ± 1%, ERJ6E Series
designator R?, comment 1k54
SMD Chip Resistor, Thick Film, 1.54 kohm, 150 V, 0805 [2012 Metric], 125 mW, ± 1%, ERJ6E Series; MPN: ERJ6ENF1541V; VoltageRating: 150V; Temp coefficient: *ppm; PowerRating: 125mW; MF: PANASONIC ELECTRONIC COMPONENTS
footprint R0805 (0805 resistor)
pins: 1, 2

## R, 2 kohm, 50 V, 0603 [1608 Metric], 100 mW, ± 1%, MCWR Series
designator R?, comment 2k
SMD Chip Resistor, Thick Film, 2 kohm, 50 V, 0603 [1608 Metric], 100 mW, ± 1%, MCWR Series; MPN: MCWR06X2001FTL; VoltageRating: 50V; Temp coefficient: *ppm; PowerRating: 100mW; MF: MULTICOMP
footprint R0402 (0402 resistor)
footprint R0603 (0603 resistor)
footprint R0805 (0805 resistor)
footprint R1206 (1206 resistor)
footprint R2512 (2512 resistor)
footprint R0201 (0201 resistor)
footprint R1210 (1210 resistor)
footprint R1812 (1812 resistor)
footprint R2010 (2010 resistor)
footprint R2512 (2512 resistor)
pins: 1, 2

## R, 2.2 kohm, 50 V, Thick Film, 0603 [1608 Metric], 100 mW, ± 1%
designator R?, comment 2k2
SMD Chip Resistor, 2.2 kohm, 50 V, Thick Film, 0603 [1608 Metric], 100 mW, ± 1%; MPN: MCWR06X2201FTL; VoltageRating: 50V; Temp coefficient: *ppm; PowerRating: 100mW; MF: MULTICOMP
footprint R0402 (0402 resistor)
footprint R0603 (0603 resistor)
footprint R0805 (0805 resistor)
footprint R1206 (1206 resistor)
footprint R2512 (2512 resistor)
footprint R0201 (0201 resistor)
footprint R1210 (1210 resistor)
footprint R1812 (1812 resistor)
footprint R2010 (2010 resistor)
footprint R2512 (2512 resistor)
pins: 1, 2

## R, 2.2 ohm, 75 V, 0603 [1608 Metric], 100 mW, ± 1%, WR06 Series
designator R?, comment 2R2
SMD Chip Resistor, 2.2 ohm, 75 V, 0603 [1608 Metric], 100 mW, ± 1%, WR06 Series; MPN: WR06W2R20FTL; VoltageRating: 75V; Temp coefficient: *ppm; PowerRating: 100mW; MF: WALSIN
footprint R0402 (0402 resistor)
footprint R0603 (0603 resistor)
footprint R0805 (0805 resistor)
footprint R1206 (1206 resistor)
footprint R2512 (2512 resistor)
footprint R0201 (0201 resistor)
footprint R1210 (1210 resistor)
footprint R1812 (1812 resistor)
footprint R2010 (2010 resistor)
footprint R2512 (2512 resistor)
pins: 1, 2

## R, 2.43 kohm, 150 V, 0805 [2012 Metric], 125 mW, ± 1%
designator R?, comment 2k43
SMD Chip Resistor, Thick Film, 2.43 kohm, 150 V, 0805 [2012 Metric], 125 mW, ± 1%; MPN: ERJ6ENF2431V; VoltageRating: 150V; Temp coefficient: *ppm; PowerRating: 125mW; MF: PANASONIC ELECTRONIC COMPONENTS
footprint R0805 (0805 resistor)
pins: 1, 2

## R, 3.3 kohm, 50 V, 0603 [1608 Metric], 100 mW, ± 1%, MCWR Series
designator R?, comment 3k3
SMD Chip Resistor, Thick Film, 3.3 kohm, 50 V, 0603 [1608 Metric], 100 mW, ± 1%, MCWR Series; MPN: MCWR06X3301FTL; VoltageRating: 50V; Temp coefficient: *ppm; PowerRating: 100mW; MF: MULTICOMP
footprint R0603 (0603 resistor)
pins: 1, 2

## R, 3.83 kohm, 75 V, 0603 [1608 Metric], 100 mW, ± 1%, MCT Series
designator R,, comment 3k83
SMD Chip Resistor, Thin Film, 3.83 kohm, 75 V, 0603 [1608 Metric], 100 mW, ± 1%, MCT Series; MPN: MCT06030C3831FP500; VoltageRating: 75V; Temp coefficient: *ppm; PowerRating: 100mW; MF: VISHAY
footprint R0603 (0603 resistor)
pins: 1, 2

## R, 4 kohm, 150 V, 0805 [2012 Metric], 125 mW, ± 1%, CRCW Series
designator R?, comment 4k
SMD Chip Resistor, Thick Film, 4 kohm, 150 V, 0805 [2012 Metric], 125 mW, ± 1%, CRCW Series; MPN: CRCW08054K00FKTA; VoltageRating: 150V; Temp coefficient: *ppm; PowerRating: 125mW; MF: VISHAY
footprint R0805 (0805 resistor)
pins: 1, 2

## R, 4.7 kohm, 75 V, 0603 [1608 Metric], 100 mW, ± 1%, WR06 Series
designator R?, comment 4k7
SMD Chip Resistor, 4.7 kohm, 75 V, 0603 [1608 Metric], 100 mW, ± 1%, WR06 Series; MPN: WR06X4701FTL; VoltageRating: 75V; Temp coefficient: *ppm; PowerRating: 100mW; MF: WALSIN
footprint R0402 (0402 resistor)
footprint R0603 (0603 resistor)
footprint R0805 (0805 resistor)
footprint R1206 (1206 resistor)
footprint R2512 (2512 resistor)
footprint R0201 (0201 resistor)
footprint R1210 (1210 resistor)
footprint R1812 (1812 resistor)
footprint R2010 (2010 resistor)
footprint R2512 (2512 resistor)
pins: 1, 2

## R, 4.75 kohm, 50 V, 0603 [1608 Metric], 100 mW, ± 1%, MCWR Series
designator R?, comment 4k75
SMD Chip Resistor, Thick Film, 4.75 kohm, 50 V, 0603 [1608 Metric], 100 mW, ± 1%, MCWR Series; MPN: MCWR06X4751FTL; VoltageRating: 50V; Temp coefficient: *ppm; PowerRating: 100mW; MF: MULTICOMP
footprint R0402 (0402 resistor)
footprint R0603 (0603 resistor)
footprint R0805 (0805 resistor)
footprint R1206 (1206 resistor)
footprint R2512 (2512 resistor)
footprint R0201 (0201 resistor)
footprint R1210 (1210 resistor)
footprint R1812 (1812 resistor)
footprint R2010 (2010 resistor)
footprint R2512 (2512 resistor)
pins: 1, 2

## R, 5.1 kohm, 50 V, 0603 [1608 Metric], 100 mW, ± 1%, MCWR Series
designator R?, comment 5k1
SMD Chip Resistor, Thick Film, 5.1 kohm, 50 V, 0603 [1608 Metric], 100 mW, ± 1%, MCWR Series; MPN: MCWR06X5101FTL; VoltageRating: 50V; Temp coefficient: *ppm; PowerRating: 100mW; MF: MULTICOMP
footprint R0402 (0402 resistor)
footprint R0603 (0603 resistor)
footprint R0805 (0805 resistor)
footprint R1206 (1206 resistor)
footprint R2512 (2512 resistor)
footprint R0201 (0201 resistor)
footprint R1210 (1210 resistor)
footprint R1812 (1812 resistor)
footprint R2010 (2010 resistor)
footprint R2512 (2512 resistor)
pins: 1, 2

## R, 5.1 Mohm, 75 V, Thick Film, 0603 [1608 Metric], 100 mW, ± 1%
designator R?, comment 5M1
SMD Chip Resistor, 5.1 Mohm, 75 V, Thick Film, 0603 [1608 Metric], 100 mW, ± 1%; MPN: MCWR06W5104FTL; VoltageRating: 75V; Temp coefficient: *ppm; PowerRating: 100mW; MF: MULTICOMP
footprint R0402 (0402 resistor)
footprint R0603 (0603 resistor)
footprint R0805 (0805 resistor)
footprint R1206 (1206 resistor)
footprint R2512 (2512 resistor)
footprint R0201 (0201 resistor)
footprint R1210 (1210 resistor)
footprint R1812 (1812 resistor)
footprint R2010 (2010 resistor)
footprint R2512 (2512 resistor)
pins: 1, 2

## R, 5.76 kohm, 75 V, 0603 [1608 Metric], 100 mW, ± 1%, WR06 Series
designator R?, comment 5k76
SMD Chip Resistor, 5.76 kohm, 75 V, 0603 [1608 Metric], 100 mW, ± 1%, WR06 Series; MPN: WR06X5761FTL; VoltageRating: 75V; Temp coefficient: *ppm; PowerRating: 100mW; MF: WALSIN
footprint R0402 (0402 resistor)
footprint R0603 (0603 resistor)
footprint R0805 (0805 resistor)
footprint R1206 (1206 resistor)
footprint R2512 (2512 resistor)
footprint R0201 (0201 resistor)
footprint R1210 (1210 resistor)
footprint R1812 (1812 resistor)
footprint R2010 (2010 resistor)
footprint R2512 (2512 resistor)
pins: 1, 2

## R, 5.76 Mohm, 150 V, 0805 [2012 Metric], 125 mW, ± 1%, CRCW Series
designator R?, comment 5M76
SMD Chip Resistor, Thick Film, 5.76 Mohm, 150 V, 0805 [2012 Metric], 125 mW, ± 1%, CRCW Series; MPN: CRCW08055M76FKEA; VoltageRating: 150V; Temp coefficient: *ppm; PowerRating: 125mW; MF: VISHAY
footprint R0402 (0402 resistor)
footprint R0603 (0603 resistor)
footprint R0805 (0805 resistor)
footprint R1206 (1206 resistor)
footprint R2512 (2512 resistor)
footprint R0201 (0201 resistor)
footprint R1210 (1210 resistor)
footprint R1812 (1812 resistor)
footprint R2010 (2010 resistor)
footprint R2512 (2512 resistor)
pins: 1, 2

## R, 6.49 kohm, 50 V, 0603 [1608 Metric], 100 mW, ± 1%, MCWR Series
designator R?, comment 6k49
SMD Chip Resistor, Thick Film, 6.49 kohm, 50 V, 0603 [1608 Metric], 100 mW, ± 1%, MCWR Series; MPN: MCWR06X6491FTL; VoltageRating: 50V; Temp coefficient: *ppm; PowerRating: 100mW; MF: MULTICOMP
footprint R0603 (0603 resistor)
pins: 1, 2

## R, 7.15 Mohm, 75 V, 0603 [1608 Metric], 100 mW, ± 1%, CRCW Series
designator R?, comment 133k
SMD Chip Resistor, Thick Film, 7.15 Mohm, 75 V, 0603 [1608 Metric], 100 mW, ± 1%, CRCW Series; MPN: CRCW06037M15FKEA.; VoltageRating: 75V; Temp coefficient: *ppm; PowerRating: 100mW; MF: VISHAY
footprint R0402 (0402 resistor)
footprint R0603 (0603 resistor)
footprint R0805 (0805 resistor)
footprint R1206 (1206 resistor)
footprint R2512 (2512 resistor)
footprint R0201 (0201 resistor)
footprint R1210 (1210 resistor)
footprint R1812 (1812 resistor)
footprint R2010 (2010 resistor)
footprint R2512 (2512 resistor)
pins: 1, 2

## R, 8.66 kohm, 50 V, 0603 [1608 Metric], 100 mW, ± 1%, MCWR Series
designator R1, comment 8k66
SMD Chip Resistor, Thick Film, 8.66 kohm, 50 V, 0603 [1608 Metric], 100 mW, ± 1%, MCWR Series; MPN: MCWR06X8661FTL; VoltageRating: 50V; Temp coefficient: *ppm; PowerRating: 100mW; MF: MULTICOMP
footprint R0603 (0603 resistor)
pins: 1, 2

## R, 9.76 kohm, 75 V, 0603 [1608 Metric], 100 mW, ± 1%, ERJ3E Series
designator R?, comment 9k76
SMD Chip Resistor, Thick Film, 9.76 kohm, 75 V, 0603 [1608 Metric], 100 mW, ± 1%, ERJ3E Series; MPN: ERJ3EKF9761V; VoltageRating: 75V; Temp coefficient: *ppm; PowerRating: 100mW; MF: PANASONIC ELECTRONIC COMPONENTS
footprint R0603 (0603 resistor)
pins: 1, 2

## R, 10 kohm, 50 V, 0603 [1608 Metric], 63 mW, ± 1%, MC Series
designator R?, comment 10k
SMD Chip Resistor, Thick Film, 10 kohm, 50 V, 0603 [1608 Metric], 63 mW, ± 1%, MC Series; MPN: MC0063W0603110K; VoltageRating: 50V; Temp coefficient: *ppm; PowerRating: 63mW; MF: MULTICOMP
footprint R0402 (0402 resistor)
footprint R0603 (0603 resistor)
footprint R0805 (0805 resistor)
footprint R1206 (1206 resistor)
footprint R2512 (2512 resistor)
footprint R0201 (0201 resistor)
footprint R1210 (1210 resistor)
footprint R1812 (1812 resistor)
footprint R2010 (2010 resistor)
footprint R2512 (2512 resistor)
pins: 1, 2

## R, 10 kohm, 50 V, 0603 [1608 Metric], 100 mW, ± 1%, MCWR Series
designator R712, comment 10k
SMD Chip Resistor, Thick Film, 10 kohm, 50 V, 0603 [1608 Metric], 100 mW, ± 1%, MCWR Series; MPN: MCWR06X1002FTL; VoltageRating: 50V; Temp coefficient: *ppm; PowerRating: 100mW; MF: MULTICOMP
footprint R0603 (0603 resistor)
pins: 1, 2

## R, 10 ohm, 50 V, 0603 [1608 Metric], 100 mW, ± 1%, MCWR Series
designator R?, comment 10R
SMD Chip Resistor, Thick Film, 10 ohm, 50 V, 0603 [1608 Metric], 100 mW, ± 1%, MCWR Series; MPN: MC0063W0603110K; VoltageRating: 50V; Temp coefficient: *ppm; PowerRating: 100mW; MF: MULTICOMP
footprint R0402 (0402 resistor)
footprint R0603 (0603 resistor)
footprint R0805 (0805 resistor)
footprint R1206 (1206 resistor)
footprint R2512 (2512 resistor)
footprint R0201 (0201 resistor)
footprint R1210 (1210 resistor)
footprint R1812 (1812 resistor)
footprint R2010 (2010 resistor)
footprint R2512 (2512 resistor)
pins: 1, 2

## R, 10.5 kohm, 50 V, 0603 [1608 Metric], 100 mW, ± 1%, MCWR Series
designator R?, comment 10k5
SMD Chip Resistor, Thick Film, 10.5 kohm, 50 V, 0603 [1608 Metric], 100 mW, ± 1%, MCWR Series; MPN: MCWR06X1052FTL; VoltageRating: 50V; Temp coefficient: *ppm; PowerRating: 100mW; MF: MULTICOMP
footprint R0402 (0402 resistor)
footprint R0603 (0603 resistor)
footprint R0805 (0805 resistor)
footprint R1206 (1206 resistor)
footprint R2512 (2512 resistor)
footprint R0201 (0201 resistor)
footprint R1210 (1210 resistor)
footprint R1812 (1812 resistor)
footprint R2010 (2010 resistor)
footprint R2512 (2512 resistor)
pins: 1, 2

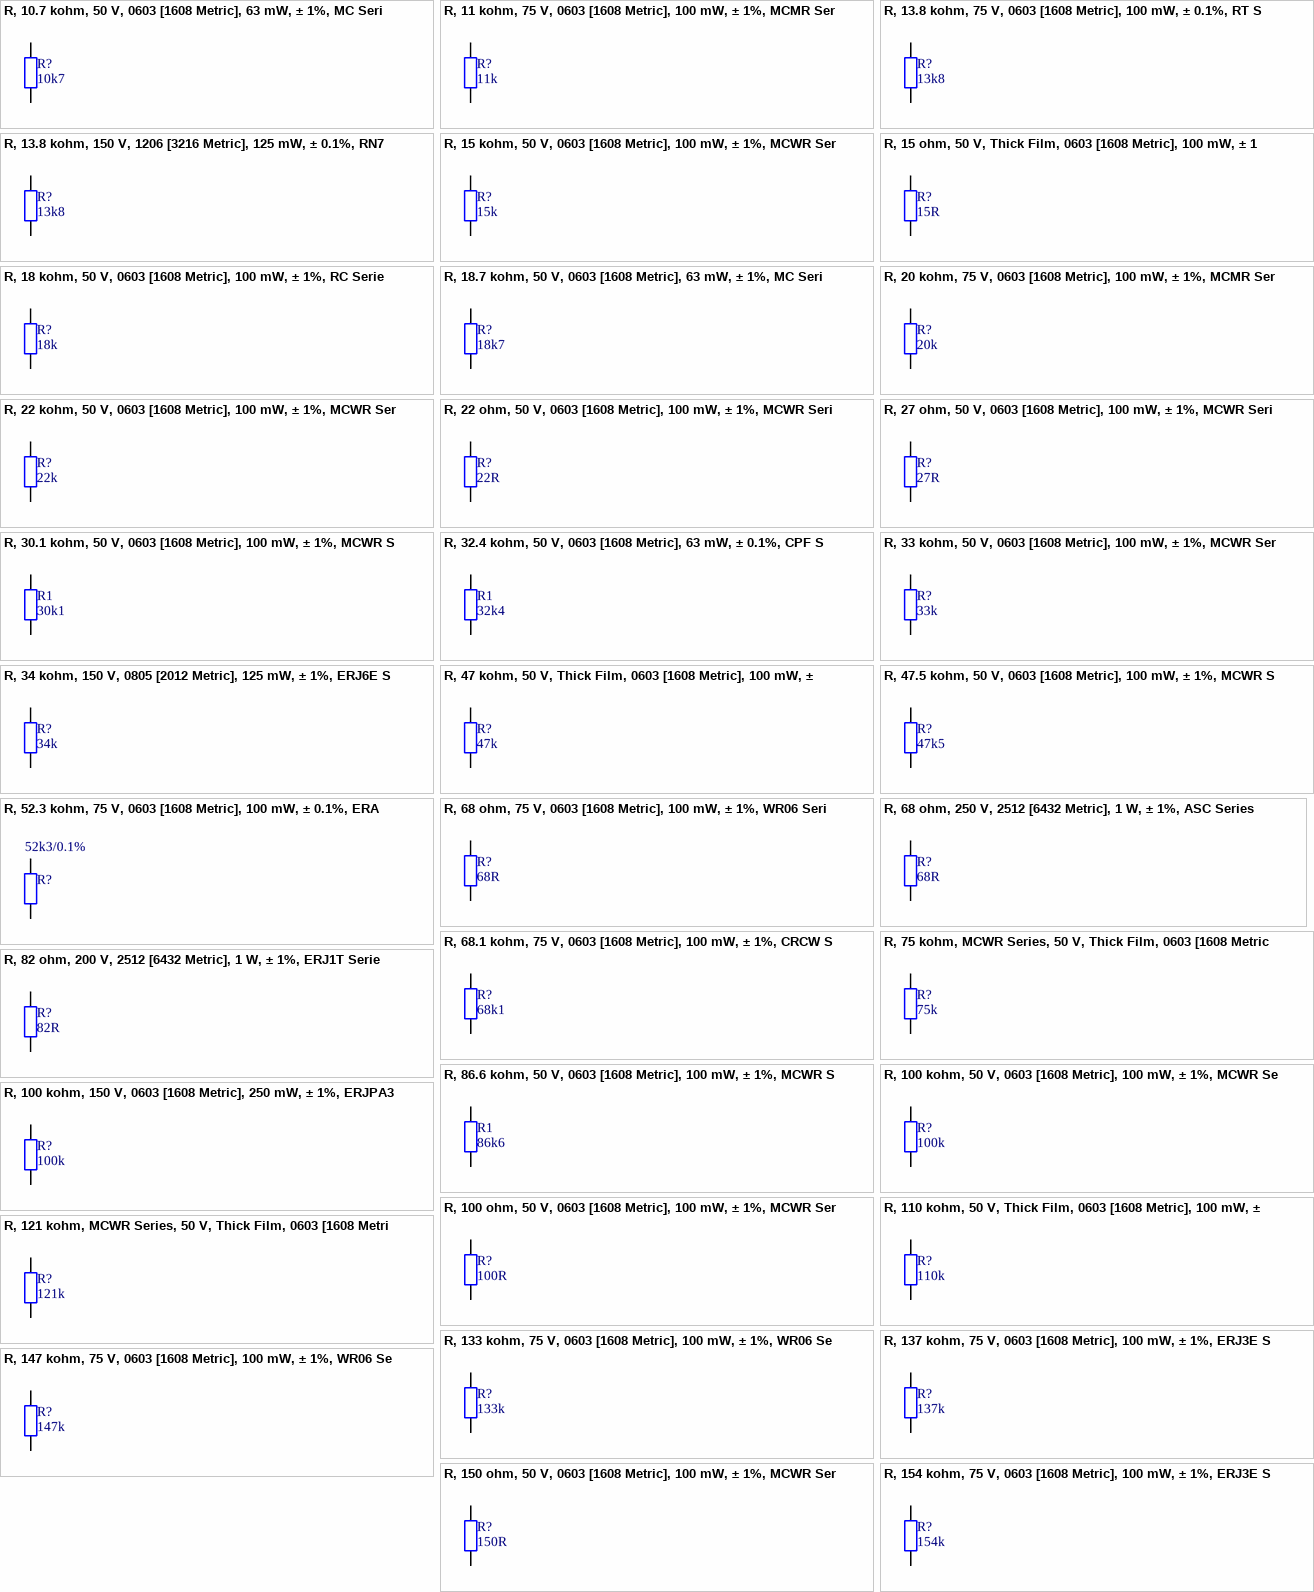
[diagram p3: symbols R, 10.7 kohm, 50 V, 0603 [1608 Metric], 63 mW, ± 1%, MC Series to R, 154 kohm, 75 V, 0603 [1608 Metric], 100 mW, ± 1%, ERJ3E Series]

## R, 10.7 kohm, 50 V, 0603 [1608 Metric], 63 mW, ± 1%, MC Series
designator R?, comment 10k7
SMD Chip Resistor, Thick Film, 10.5 kohm, 50 V, 0603 [1608 Metric], 100 mW, ± 1%, MCWR Series; MPN: MC0063W0603110K7; VoltageRating: 50V; Temp coefficient: *ppm; PowerRating: 63mW; MF: MULTICOMP
footprint R0603 (0603 resistor)
pins: 1, 2

## R, 11 kohm, 75 V, 0603 [1608 Metric], 100 mW, ± 1%, MCMR Series
designator R?, comment 11k
SMD Chip Resistor, Ceramic, 11 kohm, 75 V, 0603 [1608 Metric], 100 mW, ± 1%, MCMR Series; MPN: MCMR06X1102FTL; VoltageRating: 75V; Temp coefficient: *ppm; PowerRating: 100mW; MF: MULTICOMP
footprint R0603 (0603 resistor)
pins: 1, 2

## R, 13.8 kohm, 75 V, 0603 [1608 Metric], 100 mW, ± 0.1%, RT Series
designator R?, comment 13k8
SMD Chip Resistor, 13.8 kohm, 75 V, 0603 [1608 Metric], 100 mW, ± 0.1%, RT Series; MPN: RT0603BRD0713K8L; VoltageRating: 75V; Temp coefficient: *ppm; PowerRating: 100mW; MF: YAEGO
footprint R0603 (0603 resistor)
pins: 1, 2

## R, 13.8 kohm, 150 V, 1206 [3216 Metric], 125 mW, ± 0.1%, RN73 Seriess
designator R?, comment 13k8
SMD Chip Resistor, 13.8 kohm, 150 V, 1206 [3216 Metric], 125 mW, ± 0.1%, RN73 Series; MPN: RN732BTTD1382B25; VoltageRating: 150V; Temp coefficient: *ppm; PowerRating: 125mW; MF: KOA Speer
footprint R1206 (1206 resistor)
pins: 1, 2

## R, 15 kohm, 50 V, 0603 [1608 Metric], 100 mW, ± 1%, MCWR Series
designator R?, comment 15k
SMD Chip Resistor, Thick Film, 15 kohm, 50 V, 0603 [1608 Metric], 100 mW, ± 1%, MCWR Series; MPN: MCWR06X1502FTL; VoltageRating: 50V; Temp coefficient: *ppm; PowerRating: 100mW; MF: MULTICOMP
footprint R0603 (0603 resistor)
pins: 1, 2

## R, 15 ohm, 50 V, Thick Film, 0603 [1608 Metric], 100 mW, ± 1%
designator R?, comment 15R
SMD Chip Resistor, 15 ohm, 50 V, Thick Film, 0603 [1608 Metric], 100 mW, ± 1%; MPN: MCWR06X15R0FTL; VoltageRating: 50V; Temp coefficient: *ppm; PowerRating: 100mW; MF: MULTICOMP
footprint R0402 (0402 resistor)
footprint R0603 (0603 resistor)
footprint R0805 (0805 resistor)
footprint R1206 (1206 resistor)
footprint R2512 (2512 resistor)
footprint R0201 (0201 resistor)
footprint R1210 (1210 resistor)
footprint R1812 (1812 resistor)
footprint R2010 (2010 resistor)
footprint R2512 (2512 resistor)
pins: 1, 2

## R, 18 kohm, 50 V, 0603 [1608 Metric], 100 mW, ± 1%, RC Series
designator R?, comment 18k
SMD Chip Resistor, Thick Film, 18 kohm, 50 V, 0603 [1608 Metric], 100 mW, ± 1%, RC Series; MPN: RC0603FR-0718KL; VoltageRating: 50V; Temp coefficient: *ppm; PowerRating: 100mW; MF: YAGEO (PHYCOMP)
footprint R0603 (0603 resistor)
pins: 1, 2

## R, 18.7 kohm, 50 V, 0603 [1608 Metric], 63 mW, ± 1%, MC Series
designator R?, comment 18k7
SMD Chip Resistor, Thick Film, 18.7 kohm, 50 V, 0603 [1608 Metric], 63 mW, ± 1%, MC Series; MPN: MC0063W0603118K7; VoltageRating: 50V; Temp coefficient: *ppm; PowerRating: 100mW; MF: MULTICOMP
footprint R0402 (0402 resistor)
footprint R0603 (0603 resistor)
footprint R0805 (0805 resistor)
footprint R1206 (1206 resistor)
footprint R2512 (2512 resistor)
footprint R0201 (0201 resistor)
footprint R1210 (1210 resistor)
footprint R1812 (1812 resistor)
footprint R2010 (2010 resistor)
footprint R2512 (2512 resistor)
pins: 1, 2

## R, 20 kohm, 75 V, 0603 [1608 Metric], 100 mW, ± 1%, MCMR Series
designator R?, comment 20k
SMD Chip Resistor, Ceramic, 20 kohm, 75 V, 0603 [1608 Metric], 100 mW, ± 1%, MCMR Series; MPN: MCMR06X2002FTL; VoltageRating: 75V; Temp coefficient: *ppm; PowerRating: 100mW; MF: MULTICOMP
footprint R0603 (0603 resistor)
pins: 1, 2

## R, 22 kohm, 50 V, 0603 [1608 Metric], 100 mW, ± 1%, MCWR Series
designator R?, comment 22k
SMD Chip Resistor, Thick Film, 22 kohm, 50 V, 0603 [1608 Metric], 100 mW, ± 1%, MCWR Series; MPN: MCWR06X2202FTL; VoltageRating: 50V; Temp coefficient: *ppm; PowerRating: 100mW; MF: MULTICOMP
footprint R0603 (0603 resistor)
pins: 1, 2

## R, 22 ohm, 50 V, 0603 [1608 Metric], 100 mW, ± 1%, MCWR Series
designator R?, comment 22R
SMD Chip Resistor, Thick Film, 22 ohm, 50 V, 0603 [1608 Metric], 100 mW, ± 1%, MCWR Series; MPN: MCWR06X22R0FTL; VoltageRating: 50V; Temp coefficient: *ppm; PowerRating: 100mW; MF: MULTICOMP
footprint R0603 (0603 resistor)
pins: 1, 2

## R, 27 ohm, 50 V, 0603 [1608 Metric], 100 mW, ± 1%, MCWR Series
designator R?, comment 27R
SMD Chip Resistor, Thick Film, 27 ohm, 50 V, 0603 [1608 Metric], 100 mW, ± 1%, MCWR Series; MPN: MCWR06X27R0FTL; VoltageRating: 50V; Temp coefficient: *ppm; PowerRating: 100mW; MF: MULTICOMP
footprint R0402 (0402 resistor)
footprint R0603 (0603 resistor)
footprint R0805 (0805 resistor)
footprint R1206 (1206 resistor)
footprint R2512 (2512 resistor)
footprint R0201 (0201 resistor)
footprint R1210 (1210 resistor)
footprint R1812 (1812 resistor)
footprint R2010 (2010 resistor)
footprint R2512 (2512 resistor)
pins: 1, 2

## R, 30.1 kohm, 50 V, 0603 [1608 Metric], 100 mW, ± 1%, MCWR Series
designator R1, comment 30k1
SMD Chip Resistor, Thick Film, 30.1 kohm, 50 V, 0603 [1608 Metric], 100 mW, ± 1%, MCWR Series; MPN: MCWR06X3012FTL; VoltageRating: 50V; Temp coefficient: *ppm; PowerRating: 100mW; MF: MULTICOMP
footprint R0603 (0603 resistor)
pins: 1, 2

## R, 32.4 kohm, 50 V, 0603 [1608 Metric], 63 mW, ± 0.1%, CPF Series
designator R1, comment 32k4
SMD Chip Resistor, Thin Film, 32.4 kohm, 50 V, 0603 [1608 Metric], 63 mW, ± 0.1%, CPF Series; MPN: CPF0603B32K4E1; Precision: 1%; VoltageRating: 50V; Temp coefficient: *ppm; PowerRating: 63mW; MF: TE CONNECTIVITY
footprint R0603 (0603 resistor)
pins: 1, 2

## R, 33 kohm, 50 V, 0603 [1608 Metric], 100 mW, ± 1%, MCWR Series
designator R?, comment 33k
SMD Chip Resistor, Thick Film, 33 kohm, 50 V, 0603 [1608 Metric], 100 mW, ± 1%, MCWR Series; MPN: MCWR06X3302FTL; VoltageRating: 50V; Temp coefficient: *ppm; PowerRating: 100mW; MF: MULTICOMP
footprint R0603 (0603 resistor)
pins: 1, 2

## R, 34 kohm, 150 V, 0805 [2012 Metric], 125 mW, ± 1%, ERJ6E Series
designator R?, comment 34k
SMD Chip Resistor, Thick Film, 34 kohm, 150 V, 0805 [2012 Metric], 125 mW, ± 1%, ERJ6E Series; MPN: ERJ6ENF3402V; VoltageRating: 150V; Temp coefficient: *ppm; PowerRating: 125mW; MF: PANASONIC ELECTRONIC COMPONENTS
footprint R0805 (0805 resistor)
pins: 1, 2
